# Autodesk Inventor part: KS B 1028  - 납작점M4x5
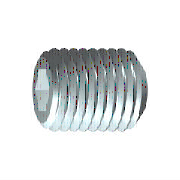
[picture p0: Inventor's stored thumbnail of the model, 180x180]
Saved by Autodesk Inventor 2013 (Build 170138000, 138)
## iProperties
IsCustomPart: 0
Created: 2009-02
Part Number: KS B 1028  - 납작점M4x5
Material: 강철, 연강
Description: 6각 소켓 머리 없는 멈춤 나사
Document SubType Name: Modeling
Standard: KS B 1028
Designer: KYOUNG IL JANG
Standards Organization: KS
Language: ko-KR
Size Designation: 납작점M4x5
Categories: <MemberInstance><Categories><Category DisplayName="조임쇠" InternalName="e4da775c-781d-43d5-af7c-5136215cf5a6" Mnemonic="FSTN"><Category DisplayName="볼트" InternalN
Density: 7.86 g/cm^3
Mass: 0.401763 g
Surface Area: 0.994256 cm^2
Volume: 0.0511149 cm^3
Author: KYOUNG IL JANG
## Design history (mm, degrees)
sketch "스케치1"
  geometry: L1 (0, 0)-(1.833, 0); L2 (5, 1.155)-(5, 2); L3 (5, 2)-(0, 2); L4 (5, 1.155)-(2.5, 1.155); L5 (2.5, 1.155)-(1.833, 0); L6 (0, -0.4)-(0, 2.4) reference; L7 (0, 2)-(0, 0)
  constraints: 13 end point, 3 parallel, 1 collinear, 1 perpendicular, 1 point on line
  dimensions: "d0" = 2.5 distance of L2.start L4.end (= INTI); "d1" = 60 deg angle of L5 L1; "d2" = 4 diameter of L3 L1 (= NND); "d3" = 2.3094 diameter of L4 L1 (= 1.1547 x SW); "d5" = 5 distance from line of L2 L3.end (= NLG)
revolve "본체" sketch "스케치1" stored, may be unused: angle "d6" = 90 deg
sketch "스케치2"
  geometry: L1 (-0.577, 1)-(0.577, 1); L2 (0.577, 1)-(1.155, 0); L3 (1.155, 0)-(0.577, -1); L4 (0.577, -1)-(-0.577, -1); L5 (-0.577, -1)-(-1.155, 0); L6 (-1.155, 0)-(-0.577, 1); A1 r 1.155 centre (0, 0) between (-0.577, 1) and (0.577, 1) reference; 2 further points
  constraints: 12 end point, 2 point on circle, 1 coincident, 1 horizontal, 11 other
extrude "슬롯" join sketch "스케치2" taper "d9" = 0 deg; stored distance "d21" = 10
workaxis "Work Axis1"
workplane "Work Plane1"
body "Solid1"
chamfer "모따기1" distance "d7" = 0.42941 (= -0.5 x GD1 + 0.5 x NND); stored, may be unused: angle "d8" = 45 deg (= FAWI), second distance "d29" = 0.42941 (= -0.5 x GD1 + 0.5 x NND)
feature "스레드" dims "d11" = 5 (= NLG), "d12" = 0
chamfer "모따기2" distance "d13" = 0.42941 (= -0.5 x GD1 + 0.5 x NND); stored, may be unused: angle "d14" = 45 deg (= FAWI), second distance "d30" = 0.42941 (= -0.5 x GD1 + 0.5 x NND)
other parameters: "NND" = 4 [user parameter; used in 5 equation terms], "NLG" = 5 [user parameter; used in 2 equation terms], "INTI" = 2.5 [user parameter; used in 1 equation term], "FAWI" = 45 deg [user parameter; used in 2 equation terms], "SW" = 2 [user parameter; used in 2 equation terms], "GD1" = 3.14117 (= THREADDIA - 1.2269 x PTC) [user parameter; used in 4 equation terms], "d4" = 0, "FAWI1" = 45 deg [user parameter], "d15" = 0, "d31" = 0, "GUL" = 0.42941 (= 0.61345 x PTC) [user parameter], "SPD" = 2.5 [user parameter], "TPU" = 14.28571 (computed from PTC) [user parameter], "TOA" = 30 deg [user parameter], "THREADDIA" = 4 [user parameter; used in 1 equation term], "PTC" = 0.7 [user parameter; used in 4 equation terms], "GAL" = 0.42941 (= 0.61345 x PTC) [user parameter], "E0" = 2.31 (= 1.155 x SW) [user parameter]
